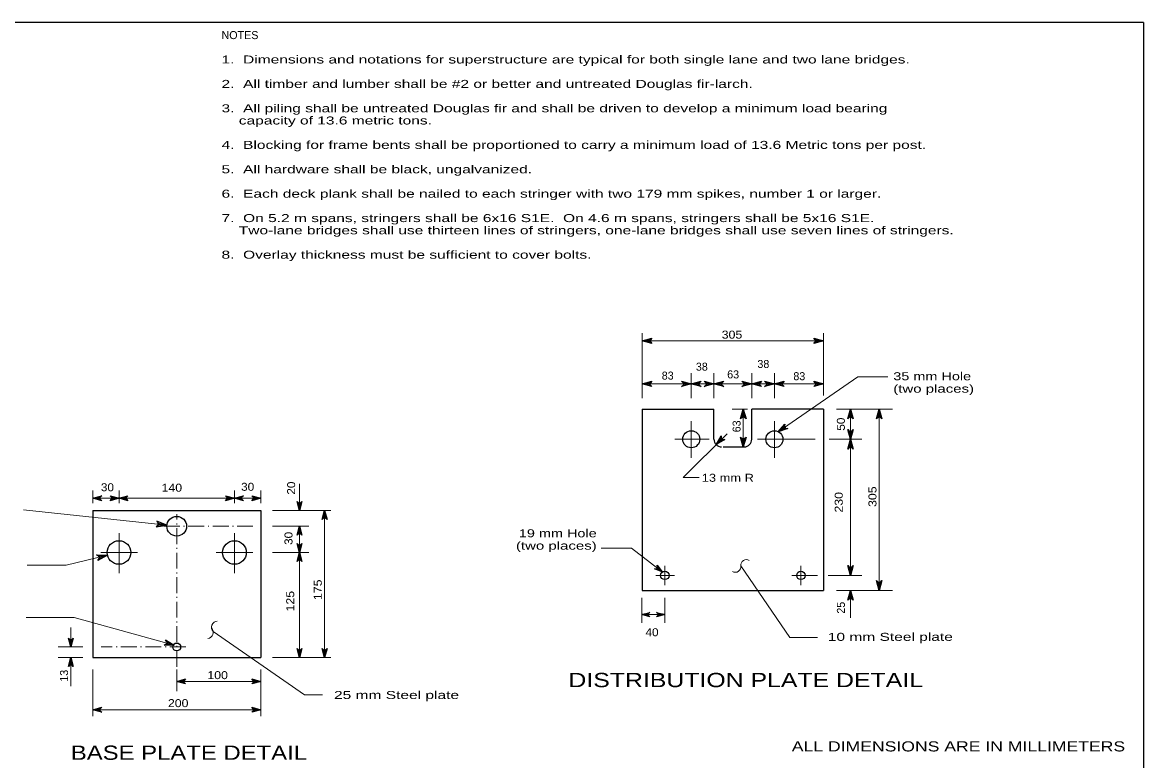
# Model space of a CAD drawing. Extents: x 13426 to 15509, y -9298 to -5111.
# Drawn here: x 15326 to 15509.2, y -5231.6 to -5111 of the extents above; entities that cross this region are included whole.
import ezdxf
from ezdxf.enums import TextEntityAlignment as Align

# ---------------------------------------------------------------- set-up
doc = ezdxf.new("R2010")
doc.units = 0
doc.header["$LTSCALE"] = 0.52
doc.linetypes.add('DOT_DASHED', pattern=[7.7, 5, -1.2, 0.3, -1.2])
for name, color, linetype, lineweight in [('1', 7, 'Continuous', 13), ('15', 7, 'Continuous', 13), ('16', 7, 'Continuous', 25), ('20', 7, 'Continuous', 13), ('3', 7, 'Continuous', 25), ('30', 7, 'Continuous', 25)]:
    doc.layers.add(name, color=color, linetype=linetype, lineweight=lineweight)
doc.layers.add('19', color=7, linetype='Continuous')

msp = doc.modelspace()

# ---------------------------------------------------------------- linework, layer by layer
at = {"layer": '1', "lineweight": 25}
for p, q in [((15427.254, -5174.207), (15438.984, -5174.207)), ((15438.984, -5179.146), (15438.984, -5174.207)), ((15456.888, -5174.207), (15445.158, -5174.207)), ((15445.158, -5179.146), (15445.158, -5174.207)), ((15456.888, -5174.207), (15456.888, -5203.841)), ((15440.506, -5180.38), (15444.21, -5180.38)), ((15337.516, -5190.78), (15364.946, -5190.78)), ((15364.946, -5190.78), (15364.946, -5214.782))]:
    msp.add_line(p, q, dxfattribs=at)
for points in [[(15427.254, -5174.207), (15427.254, -5203.841), (15456.888, -5203.841)], [(15337.516, -5190.78), (15337.516, -5214.782), (15364.946, -5214.782)]]:
    msp.add_lwpolyline(points, dxfattribs=at)
for centre, start, end in [((15440.2187, -5179.1457), 180, 269.99999), ((15443.923, -5179.1457), 270, 0)]:
    msp.add_arc(centre, 1.2348, start, end, dxfattribs=at)
at = {"layer": '15'}
for p, q in [((15427.254, -5172.442), (15427.254, -5161.793)), ((15456.888, -5172.004), (15456.888, -5161.793)), ((15427.254, -5163.056), (15456.888, -5163.056)), ((15435.28, -5168.349), (15435.28, -5172.442)), ((15438.984, -5172.442), (15438.984, -5168.349)), ((15445.158, -5172.442), (15445.158, -5168.349)), ((15448.862, -5168.349), (15448.862, -5172.442)), ((15427.254, -5170.104), (15435.28, -5170.104)), ((15448.862, -5170.104), (15456.888, -5170.104)), ((15444.45, -5174.207), (15441.946, -5174.207)), ((15443.777, -5174.207), (15443.777, -5180.38)), ((15459.01, -5174.207), (15468.156, -5174.207)), ((15465.979, -5174.207), (15465.979, -5203.841)), ((15435.28, -5182.196), (15435.28, -5176.197)), ((15448.862, -5182.196), (15448.862, -5176.197)), ((15432.566, -5179.146), (15438.189, -5179.146)), ((15446.095, -5179.146), (15455.503, -5179.146)), ((15463.148, -5179.146), (15457.802, -5179.146)), ((15337.516, -5189.591), (15337.516, -5187.514)), ((15341.802, -5189.591), (15341.802, -5187.514)), ((15360.66, -5187.514), (15360.66, -5189.591)), ((15364.946, -5189.591), (15364.946, -5187.514)), ((15371.287, -5186.395), (15371.287, -5190.78)), ((15349.633, -5193.18), (15326.19, -5190.653)), ((15366.882, -5190.78), (15376.386, -5190.78)), ((15375.39, -5190.78), (15375.39, -5214.782)), ((15372.833, -5193.352), (15366.882, -5193.352)), ((15341.802, -5200.993), (15341.802, -5194.507)), ((15360.66, -5200.993), (15360.66, -5194.507)), ((15425.527, -5196.92), (15420.534, -5196.92)), ((15430.542, -5200.815), (15425.527, -5196.92)), ((15339.928, -5198.091), (15333.177, -5199.724)), ((15338.839, -5197.638), (15344.826, -5197.638)), ((15357.698, -5197.638), (15363.67, -5197.638)), ((15372.833, -5197.638), (15366.882, -5197.638)), ((15326.778, -5199.724), (15333.177, -5199.724)), ((15430.958, -5202.996), (15430.958, -5199.832)), ((15453.184, -5202.996), (15453.184, -5199.832)), ((15429.464, -5201.372), (15432.552, -5201.372)), ((15451.69, -5201.372), (15455.886, -5201.372)), ((15457.61, -5201.372), (15463.148, -5201.372)), ((15459.01, -5203.841), (15468.156, -5203.841)), ((15461.261, -5203.841), (15461.261, -5208.309)), ((15427.195, -5205.021), (15427.195, -5209.115)), ((15430.94, -5205.021), (15430.94, -5209.115)), ((15427.195, -5207.773), (15430.94, -5207.773)), ((15333.926, -5209.916), (15333.926, -5213.067)), ((15331.856, -5213.067), (15335.898, -5213.067)), ((15335.898, -5214.782), (15331.856, -5214.782)), ((15333.926, -5219.488), (15333.926, -5214.782)), ((15366.882, -5214.782), (15376.386, -5214.782)), ((15337.516, -5216.776), (15337.516, -5224.393)), ((15351.231, -5216.776), (15351.231, -5219.594)), ((15364.946, -5216.776), (15364.946, -5224.393)), ((15351.231, -5218.693), (15364.946, -5218.693)), ((15337.516, -5223.316), (15364.946, -5223.316))]:
    msp.add_line(p, q, dxfattribs=at)
at = {"layer": '15', "linetype": 'DOT_DASHED'}
for p, q in [((15351.231, -5220.293), (15351.231, -5191.377)), ((15349.113, -5193.352), (15363.67, -5193.352)), ((15352.711, -5213.067), (15338.885, -5213.067))]:
    msp.add_line(p, q, dxfattribs=at)
at = {"layer": '15'}
for points in [[(15449.479, -5177.939), (15462.467, -5168.941), (15467.392, -5168.941)], [(15435.28, -5170.104), (15438.984, -5170.104), (15445.158, -5170.104), (15448.862, -5170.104)], [(15461.261, -5174.207), (15461.261, -5179.146), (15461.261, -5201.372)], [(15441.112, -5178.228), (15433.973, -5185.368), (15436.554, -5185.368)], [(15337.516, -5188.779), (15341.802, -5188.779), (15360.66, -5188.779), (15364.946, -5188.779)], [(15371.287, -5193.352), (15371.287, -5197.638), (15371.287, -5214.782)], [(15443.363, -5199.822), (15451.348, -5211.536), (15455.894, -5211.536)], [(15350.832, -5212.756), (15334.483, -5208.233), (15326.663, -5208.233)], [(15375.044, -5220.893), (15372.086, -5220.893), (15357.169, -5210.546)]]:
    msp.add_lwpolyline(points, dxfattribs=at)
for centre, radius, start, end in [((15444.2892, -5199.7357), 0.9305, 59.84377, 185.31451), ((15442.4404, -5199.9458), 0.9305, 242.1777, 7.64844), ((15357.9454, -5209.8646), 1.0336, 95.80811, 221.27884), ((15356.1688, -5210.6821), 1.0336, 278.14203, 43.61277)]:
    msp.add_arc(centre, radius, start, end, dxfattribs=at)
at = {"layer": '16'}
for points in [[(15428.607, -5163.233), (15428.857, -5163.494), (15427.254, -5163.056), (15428.857, -5162.619), (15428.607, -5162.879), (15427.254, -5163.056), (15428.607, -5163.233), (15428.43, -5163.056), (15428.607, -5162.879)], [(15455.535, -5162.879), (15455.285, -5162.619), (15456.888, -5163.056), (15455.285, -5163.494), (15455.535, -5163.233), (15456.888, -5163.056), (15455.535, -5162.879), (15455.712, -5163.056), (15455.535, -5163.233)], [(15428.607, -5170.281), (15428.857, -5170.541), (15427.254, -5170.104), (15428.857, -5169.667), (15428.607, -5169.927), (15427.254, -5170.104), (15428.607, -5170.281), (15428.43, -5170.104), (15428.607, -5169.927)], [(15433.926, -5169.927), (15433.676, -5169.667), (15435.28, -5170.104), (15433.676, -5170.541), (15433.926, -5170.281), (15435.28, -5170.104), (15433.926, -5169.927), (15434.103, -5170.104), (15433.926, -5170.281)], [(15436.633, -5170.281), (15436.883, -5170.541), (15435.28, -5170.104), (15436.883, -5169.667), (15436.633, -5169.927), (15435.28, -5170.104), (15436.633, -5170.281), (15436.456, -5170.104), (15436.633, -5169.927)], [(15437.631, -5169.927), (15437.381, -5169.667), (15438.984, -5170.104), (15437.381, -5170.541), (15437.631, -5170.281), (15438.984, -5170.104), (15437.631, -5169.927), (15437.808, -5170.104), (15437.631, -5170.281)], [(15440.337, -5170.281), (15440.587, -5170.541), (15438.984, -5170.104), (15440.587, -5169.667), (15440.337, -5169.927), (15438.984, -5170.104), (15440.337, -5170.281), (15440.16, -5170.104), (15440.337, -5169.927)], [(15443.804, -5169.927), (15443.555, -5169.667), (15445.158, -5170.104), (15443.555, -5170.541), (15443.804, -5170.281), (15445.158, -5170.104), (15443.804, -5169.927), (15443.982, -5170.104), (15443.804, -5170.281)], [(15446.511, -5170.281), (15446.761, -5170.541), (15445.158, -5170.104), (15446.761, -5169.667), (15446.511, -5169.927), (15445.158, -5170.104), (15446.511, -5170.281), (15446.334, -5170.104), (15446.511, -5169.927)], [(15447.509, -5169.927), (15447.259, -5169.667), (15448.862, -5170.104), (15447.259, -5170.541), (15447.509, -5170.281), (15448.862, -5170.104), (15447.509, -5169.927), (15447.686, -5170.104), (15447.509, -5170.281)], [(15450.215, -5170.281), (15450.465, -5170.541), (15448.862, -5170.104), (15450.465, -5169.667), (15450.215, -5169.927), (15448.862, -5170.104), (15450.215, -5170.281), (15450.038, -5170.104), (15450.215, -5169.927)], [(15455.535, -5169.927), (15455.285, -5169.667), (15456.888, -5170.104), (15455.285, -5170.541), (15455.535, -5170.281), (15456.888, -5170.104), (15455.535, -5169.927), (15455.712, -5170.104), (15455.535, -5170.281)], [(15443.6, -5175.56), (15443.34, -5175.81), (15443.777, -5174.207), (15444.214, -5175.81), (15443.954, -5175.56), (15443.777, -5174.207), (15443.6, -5175.56), (15443.777, -5175.383), (15443.954, -5175.56)], [(15461.084, -5175.56), (15460.824, -5175.81), (15461.261, -5174.207), (15461.698, -5175.81), (15461.438, -5175.56), (15461.261, -5174.207), (15461.084, -5175.56), (15461.261, -5175.383), (15461.438, -5175.56)], [(15465.802, -5175.56), (15465.542, -5175.81), (15465.979, -5174.207), (15466.416, -5175.81), (15466.156, -5175.56), (15465.979, -5174.207), (15465.802, -5175.56), (15465.979, -5175.383), (15466.156, -5175.56)], [(15450.692, -5177.314), (15451.045, -5177.385), (15449.479, -5177.939), (15450.547, -5176.667), (15450.49, -5177.023), (15449.479, -5177.939), (15450.692, -5177.314), (15450.446, -5177.269), (15450.49, -5177.023)], [(15440.4, -5179.168), (15440.76, -5179.175), (15439.318, -5180), (15440.142, -5178.557), (15440.149, -5178.918), (15439.318, -5180), (15440.4, -5179.168), (15440.149, -5179.168), (15440.149, -5178.918)], [(15461.438, -5177.792), (15461.698, -5177.543), (15461.261, -5179.146), (15460.824, -5177.543), (15461.084, -5177.792), (15461.261, -5179.146), (15461.438, -5177.792), (15461.261, -5177.97), (15461.084, -5177.792)], [(15443.954, -5179.027), (15444.214, -5178.777), (15443.777, -5180.38), (15443.34, -5178.777), (15443.6, -5179.027), (15443.777, -5180.38), (15443.954, -5179.027), (15443.777, -5179.204), (15443.6, -5179.027)], [(15461.084, -5180.499), (15460.824, -5180.749), (15461.261, -5179.146), (15461.698, -5180.749), (15461.438, -5180.499), (15461.261, -5179.146), (15461.084, -5180.499), (15461.261, -5180.322), (15461.438, -5180.499)], [(15338.747, -5188.94), (15338.974, -5189.177), (15337.516, -5188.779), (15338.974, -5188.382), (15338.747, -5188.618), (15337.516, -5188.779), (15338.747, -5188.94), (15338.586, -5188.779), (15338.747, -5188.618)], [(15340.572, -5188.618), (15340.345, -5188.382), (15341.802, -5188.779), (15340.345, -5189.177), (15340.572, -5188.94), (15341.802, -5188.779), (15340.572, -5188.618), (15340.733, -5188.779), (15340.572, -5188.94)], [(15343.033, -5188.94), (15343.26, -5189.177), (15341.802, -5188.779), (15343.26, -5188.382), (15343.033, -5188.618), (15341.802, -5188.779), (15343.033, -5188.94), (15342.872, -5188.779), (15343.033, -5188.618)], [(15359.43, -5188.618), (15359.203, -5188.382), (15360.66, -5188.779), (15359.203, -5189.177), (15359.43, -5188.94), (15360.66, -5188.779), (15359.43, -5188.618), (15359.591, -5188.779), (15359.43, -5188.94)], [(15361.891, -5188.94), (15362.118, -5189.177), (15360.66, -5188.779), (15362.118, -5188.382), (15361.891, -5188.618), (15360.66, -5188.779), (15361.891, -5188.94), (15361.73, -5188.779), (15361.891, -5188.618)], [(15363.716, -5188.618), (15363.489, -5188.382), (15364.946, -5188.779), (15363.489, -5189.177), (15363.716, -5188.94), (15364.946, -5188.779), (15363.716, -5188.618), (15363.877, -5188.779), (15363.716, -5188.94)], [(15371.448, -5189.55), (15371.684, -5189.323), (15371.287, -5190.78), (15370.889, -5189.323), (15371.126, -5189.55), (15371.287, -5190.78), (15371.448, -5189.55), (15371.287, -5189.711), (15371.126, -5189.55)], [(15375.229, -5192.011), (15374.993, -5192.238), (15375.39, -5190.78), (15375.788, -5192.238), (15375.551, -5192.011), (15375.39, -5190.78), (15375.229, -5192.011), (15375.39, -5191.85), (15375.551, -5192.011)], [(15348.156, -5193.213), (15347.857, -5193.464), (15349.633, -5193.18), (15347.959, -5192.523), (15348.197, -5192.833), (15349.633, -5193.18), (15348.156, -5193.213), (15348.367, -5193.043), (15348.197, -5192.833)], [(15371.126, -5194.582), (15370.889, -5194.809), (15371.287, -5193.352), (15371.684, -5194.809), (15371.448, -5194.582), (15371.287, -5193.352), (15371.126, -5194.582), (15371.287, -5194.421), (15371.448, -5194.582)], [(15371.448, -5196.407), (15371.684, -5196.18), (15371.287, -5197.638), (15370.889, -5196.18), (15371.126, -5196.407), (15371.287, -5197.638), (15371.448, -5196.407), (15371.287, -5196.568), (15371.126, -5196.407)], [(15338.459, -5198.249), (15338.13, -5198.039), (15339.928, -5198.091), (15338.353, -5198.959), (15338.549, -5198.622), (15339.928, -5198.091), (15338.459, -5198.249), (15338.69, -5198.391), (15338.549, -5198.622)], [(15371.126, -5198.868), (15370.889, -5199.095), (15371.287, -5197.638), (15371.684, -5199.095), (15371.448, -5198.868), (15371.287, -5197.638), (15371.126, -5198.868), (15371.287, -5198.707), (15371.448, -5198.868)], [(15429.752, -5200.017), (15429.721, -5199.722), (15430.542, -5200.815), (15429.28, -5200.29), (15429.574, -5200.247), (15430.542, -5200.815), (15429.752, -5200.017), (15429.778, -5200.221), (15429.574, -5200.247)], [(15461.438, -5200.018), (15461.698, -5199.768), (15461.261, -5201.372), (15460.824, -5199.768), (15461.084, -5200.018), (15461.261, -5201.372), (15461.438, -5200.018), (15461.261, -5200.195), (15461.084, -5200.018)], [(15466.156, -5202.488), (15466.416, -5202.238), (15465.979, -5203.841), (15465.542, -5202.238), (15465.802, -5202.488), (15465.979, -5203.841), (15466.156, -5202.488), (15465.979, -5202.665), (15465.802, -5202.488)], [(15461.084, -5205.194), (15460.824, -5205.444), (15461.261, -5203.841), (15461.698, -5205.444), (15461.438, -5205.194), (15461.261, -5203.841), (15461.084, -5205.194), (15461.261, -5205.017), (15461.438, -5205.194)], [(15428.308, -5207.919), (15428.514, -5208.133), (15427.195, -5207.773), (15428.514, -5207.414), (15428.308, -5207.628), (15427.195, -5207.773), (15428.308, -5207.919), (15428.163, -5207.773), (15428.308, -5207.628)], [(15429.827, -5207.628), (15429.621, -5207.414), (15430.94, -5207.773), (15429.621, -5208.133), (15429.827, -5207.919), (15430.94, -5207.773), (15429.827, -5207.628), (15429.972, -5207.773), (15429.827, -5207.919)], [(15334.087, -5211.837), (15334.324, -5211.61), (15333.926, -5213.067), (15333.529, -5211.61), (15333.766, -5211.837), (15333.926, -5213.067), (15334.087, -5211.837), (15333.926, -5211.998), (15333.766, -5211.837)], [(15349.591, -5212.231), (15349.422, -5211.918), (15350.832, -5212.756), (15349.192, -5212.75), (15349.498, -5212.568), (15350.832, -5212.756), (15349.591, -5212.231), (15349.713, -5212.446), (15349.498, -5212.568)], [(15371.448, -5213.551), (15371.684, -5213.324), (15371.287, -5214.782), (15370.889, -5213.324), (15371.126, -5213.551), (15371.287, -5214.782), (15371.448, -5213.551), (15371.287, -5213.712), (15371.126, -5213.551)], [(15375.551, -5213.551), (15375.788, -5213.324), (15375.39, -5214.782), (15374.993, -5213.324), (15375.229, -5213.551), (15375.39, -5214.782), (15375.551, -5213.551), (15375.39, -5213.712), (15375.229, -5213.551)], [(15333.766, -5216.012), (15333.529, -5216.239), (15333.926, -5214.782), (15334.324, -5216.239), (15334.087, -5216.012), (15333.926, -5214.782), (15333.766, -5216.012), (15333.926, -5215.851), (15334.087, -5216.012)], [(15352.461, -5218.854), (15352.689, -5219.091), (15351.231, -5218.693), (15352.689, -5218.296), (15352.461, -5218.533), (15351.231, -5218.693), (15352.461, -5218.854), (15352.301, -5218.693), (15352.461, -5218.533)], [(15363.716, -5218.533), (15363.489, -5218.296), (15364.946, -5218.693), (15363.489, -5219.091), (15363.716, -5218.854), (15364.946, -5218.693), (15363.716, -5218.533), (15363.877, -5218.693), (15363.716, -5218.854)], [(15338.747, -5223.477), (15338.974, -5223.714), (15337.516, -5223.316), (15338.974, -5222.919), (15338.747, -5223.155), (15337.516, -5223.316), (15338.747, -5223.477), (15338.586, -5223.316), (15338.747, -5223.155)], [(15363.716, -5223.155), (15363.489, -5222.919), (15364.946, -5223.316), (15363.489, -5223.714), (15363.716, -5223.477), (15364.946, -5223.316), (15363.716, -5223.155), (15363.877, -5223.316), (15363.716, -5223.477)]]:
    msp.add_lwpolyline(points, dxfattribs=at)
at = {"layer": '3'}
for centre, radius in [((15435.2797, -5179.1457), 1.3891), ((15448.862, -5179.1457), 1.3891), ((15351.231, -5193.3519), 1.6072), ((15341.8023, -5197.6378), 1.9287), ((15360.6605, -5197.6378), 1.9287), ((15430.958, -5201.3713), 0.6946), ((15453.1837, -5201.3713), 0.6946), ((15351.231, -5213.0672), 0.6429)]:
    msp.add_circle(centre, radius, dxfattribs=at)
at = {"layer": '30'}
for p, q in [((15509.151, -5111.044), (15181.119, -5111.044)), ((15509.151, -5111.081), (15509.151, -5323.3))]:
    msp.add_line(p, q, dxfattribs=at)

# ---------------------------------------------------------------- texts
at = {"layer": '19'}
msp.add_text('NOTES', height=1.307, dxfattribs=at).set_placement((15358.548, -5113.768))
for s, width, p in [('1.  Dimensions and notations for superstructure are typical for both single lane and two lane bridges.', 1.45, (15358.548, -5117.754)), ('2.  All timber and lumber shall be #2 or better and untreated Douglas fir-larch.', 1.45, (15358.548, -5121.74)), ('3.  All piling shall be untreated Douglas fir and shall be driven to develop a minimum load bearing', 1.45, (15358.548, -5125.726)), ('    capacity of 13.6 metric tons.', 1.45, (15358.548, -5127.719)), ('4.  Blocking for frame bents shall be proportioned to carry a minimum load of 13.6 Metric tons per post.', 1.45, (15358.548, -5131.705)), ('5.  All hardware shall be black, ungalvanized.', 1.45, (15358.548, -5135.691)), ('6.  Each deck plank shall be nailed to each stringer with two 179 mm spikes, number 1 or larger.', 1.45, (15358.548, -5139.677)), ('7.  On 5.2 m spans, stringers shall be 6x16 S1E.  On 4.6 m spans, stringers shall be 5x16 S1E.', 1.45, (15358.548, -5143.663)), ('    Two-lane bridges shall use thirteen lines of stringers, one-lane bridges shall use seven lines of stringers.', 1.45, (15358.548, -5145.656)), ('8.  Overlay thickness must be sufficient to cover bolts.', 1.45, (15358.548, -5149.642)), ('35 mm Hole', 1.35, (15468.268, -5169.498)), ('(two places)', 1.4, (15468.268, -5171.526)), ('10 mm Steel plate', 1.45, (15457.575, -5212.072)), ('25 mm Steel plate', 1.45, (15376.921, -5221.57))]:
    msp.add_text(s, height=1.307, dxfattribs=dict(at, width=width)).set_placement(p)
for s, height, width, p in [('305', 1.307, 1.15, (15441.9245, -5162.703)), ('13 mm R', 1.307, 1.2, (15441.245, -5186.084)), ('30', 1.307, 1.1, (15339.91, -5187.634)), ('140', 1.307, 1.15, (15350.4315, -5187.705)), ('30', 1.307, 1.1, (15362.817, -5187.556)), ('40', 1.307, 1.1, (15428.862, -5211.32)), ('100', 1.307, 1.15, (15357.9135, -5218.326)), ('200', 1.307, 1.15, (15351.4685, -5222.899)), ('ALL DIMENSIONS ARE IN MILLIMETERS', 1.653, 1.3, (15478.9175, -5230.138))]:
    msp.add_text(s, height=height, dxfattribs=dict(at, width=width)).set_placement(p, align=Align.CENTER)
for s, p in [('38', (15436.9985, -5167.934)), ('38', (15447.0495, -5167.489)), ('83', (15431.4235, -5169.392)), ('63', (15442.1135, -5169.197)), ('83', (15452.9215, -5169.489))]:
    msp.add_text(s, height=1.307, dxfattribs=at).set_placement(p, align=Align.CENTER)
for s, p in [('63', (15443.329, -5177.035)), ('25', (15460.365, -5206.661)), ('13', (15333.478, -5217.776))]:
    msp.add_text(s, height=1.307, rotation=90, dxfattribs=at).set_placement(p, align=Align.CENTER)
for s, width, p in [('50', 1.1, (15460.359, -5176.6715)), ('20', 1.1, (15370.57, -5187.1215)), ('230', 1.15, (15460.012, -5189.433)), ('305', 1.15, (15465.521, -5188.516)), ('30', 1.1, (15370.139, -5195.3295)), ('175', 1.15, (15374.917, -5203.728)), ('125', 1.15, (15370.422, -5205.586))]:
    msp.add_text(s, height=1.307, rotation=90, dxfattribs=dict(at, width=width)).set_placement(p, align=Align.CENTER)
for s, width, p in [('19 mm Hole', 1.35, (15419.828, -5195.147)), ('(two places)', 1.4, (15419.828, -5197.175))]:
    msp.add_text(s, height=1.307, dxfattribs=dict(at, width=width)).set_placement(p, align=Align.RIGHT)
at = {"layer": '20'}
for s, width, p in [('DISTRIBUTION PLATE DETAIL', 1.3, (15444.1645, -5219.637)), ('BASE PLATE DETAIL', 1.25, (15353.2255, -5231.508))]:
    msp.add_text(s, height=2.333, dxfattribs=dict(at, width=width)).set_placement(p, align=Align.CENTER)

doc.saveas('drawing.dxf')
